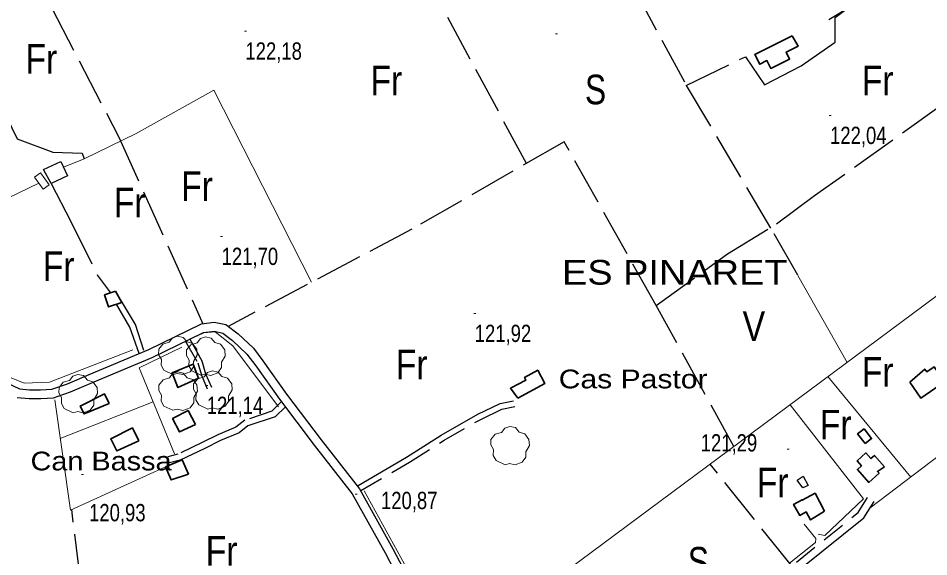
# Model space of a CAD drawing. Extents: x 483855 to 488461, y 4388206 to 4391419.
# Drawn here: x 485066.1 to 485527.5, y 4389100 to 4389372.8 of the extents above; entities that cross this region are included whole.
import ezdxf
from ezdxf.enums import TextEntityAlignment as Align

# ---------------------------------------------------------------- set-up
doc = ezdxf.new("R2010")
doc.units = 0
doc.header["$LTSCALE"] = 4
doc.linetypes.add('LONG_DASHED', pattern=[7.5, 6, -1.5])
doc.linetypes.add('MEDIUM_DASHED', pattern=[4.5, 3, -1.5])
for name, color, linetype, lineweight in [('21', 7, 'Continuous', 25), ('25', 7, 'LONG_DASHED', 25), ('29', 7, 'Continuous', 13), ('36', 7, 'Continuous', 25), ('38', 7, 'Continuous', 25), ('47', 7, 'Continuous', 35), ('51', 7, 'Continuous', 13), ('7', 7, 'Continuous', 13)]:
    doc.layers.add(name, color=color, linetype=linetype, lineweight=lineweight)
doc.layers.add('31', color=7, linetype='Continuous')
doc.layers.add('5', color=7, linetype='Continuous')

msp = doc.modelspace()

# ---------------------------------------------------------------- linework, layer by layer
at = {"layer": '21'}
for points in [[(485078.93, 4389296.12), (485087.7, 4389300.19), (485091.01, 4389293.07), (485082.84, 4389289.15)], [(485460.86, 4389138.84), (485463.86, 4389140.95), (485466.49, 4389136.15), (485463.64, 4389135.02)]]:
    msp.add_lwpolyline(points, close=True, dxfattribs=at)
at = {"layer": '25'}
for p, q in [((485428.79, 4389155.91), (485389.3, 4389227.39)), ((485458.03, 4389095.54), (485416.71, 4389146.95))]:
    msp.add_line(p, q, dxfattribs=at)
for points in [[(485302.1, 4389523.63), (485349.42, 4389440.89), (485404.65, 4389338.81)], [(485323.65, 4389299.28), (485272, 4389394.93), (485227.49, 4389486.7)], [(485069.15, 4389404.46), (485117.24, 4389312.31), (485159.64, 4389218.08)], [(485404.65, 4389338.81), (485434.63, 4389353.26), (485444.25, 4389339.03), (485462.92, 4389348.66), (485480.07, 4389360.62), (485480.13, 4389373.22), (485484.8, 4389376.81)], [(485558.17, 4389345.99), (485469.7, 4389282.81), (485447.41, 4389266.34)], [(485404.65, 4389338.81), (485448.95, 4389263.72), (485461.14, 4389242.59)], [(485057.27, 4389329.54), (485060.13, 4389322.87), (485065.48, 4389311.78), (485083.57, 4389304.98), (485098.49, 4389304.48), (485099.47, 4389301.63)], [(485389.3, 4389227.39), (485342.81, 4389310.28), (485265.54, 4389265.9), (485172.46, 4389216.76)], [(485082.84, 4389289.15), (485092.77, 4389269.89), (485106.32, 4389242.46), (485112.88, 4389233.76)], [(485389.3, 4389227.39), (485425.49, 4389253.41), (485447.14, 4389266.79)], [(485110.93, 4388988.41), (485094.88, 4389085.06), (485097.72, 4389087.76), (485093.16, 4389123.91)]]:
    msp.add_lwpolyline(points, dxfattribs=at)
at = {"layer": '29'}
for points in [[(485144.45, 4389192.38), (485139.91, 4389194.5), (485138.5, 4389197.04), (485138.6, 4389200.02), (485137.23, 4389202.43), (485137.27, 4389205.18), (485139.43, 4389207.78), (485142.62, 4389208.78), (485144.27, 4389210.97), (485146.84, 4389211.8), (485149.7, 4389211.15), (485151.65, 4389208.88), (485154.46, 4389208.06), (485156.59, 4389205.21), (485156.83, 4389202.08), (485154.95, 4389198.93), (485154.95, 4389196.25), (485153.13, 4389193.64), (485149.51, 4389192.3), (485146.74, 4389192.93)], [(485158.55, 4389192.02), (485154.01, 4389194.14), (485152.6, 4389196.68), (485152.7, 4389199.66), (485151.33, 4389202.07), (485151.37, 4389204.82), (485153.53, 4389207.42), (485156.72, 4389208.42), (485158.37, 4389210.61), (485160.94, 4389211.44), (485163.8, 4389210.79), (485165.75, 4389208.52), (485168.56, 4389207.7), (485170.69, 4389204.85), (485170.93, 4389201.72), (485169.05, 4389198.57), (485169.05, 4389195.89), (485167.23, 4389193.28), (485163.61, 4389191.94), (485160.84, 4389192.57)], [(485144.48, 4389174.22), (485139.94, 4389176.34), (485138.53, 4389178.88), (485138.63, 4389181.86), (485137.26, 4389184.27), (485137.3, 4389187.02), (485139.46, 4389189.62), (485142.65, 4389190.62), (485144.3, 4389192.81), (485146.87, 4389193.64), (485149.73, 4389192.99), (485151.68, 4389190.72), (485154.49, 4389189.9), (485156.62, 4389187.05), (485156.86, 4389183.92), (485154.98, 4389180.77), (485154.98, 4389178.09), (485153.16, 4389175.48), (485149.54, 4389174.14), (485146.77, 4389174.77)], [(485162.1, 4389174.85), (485157.56, 4389176.97), (485156.15, 4389179.51), (485156.25, 4389182.49), (485154.88, 4389184.9), (485154.92, 4389187.65), (485157.08, 4389190.25), (485160.27, 4389191.25), (485161.92, 4389193.44), (485164.49, 4389194.27), (485167.35, 4389193.62), (485169.3, 4389191.35), (485172.11, 4389190.53), (485174.24, 4389187.68), (485174.48, 4389184.55), (485172.6, 4389181.4), (485172.6, 4389178.72), (485170.78, 4389176.11), (485167.16, 4389174.77), (485164.39, 4389175.4)], [(485093.92, 4389173.01), (485089.38, 4389175.13), (485087.97, 4389177.67), (485088.07, 4389180.65), (485086.7, 4389183.06), (485086.74, 4389185.81), (485088.9, 4389188.41), (485092.09, 4389189.41), (485093.74, 4389191.6), (485096.31, 4389192.43), (485099.17, 4389191.78), (485101.12, 4389189.51), (485103.93, 4389188.69), (485106.06, 4389185.84), (485106.3, 4389182.71), (485104.42, 4389179.56), (485104.42, 4389176.88), (485102.6, 4389174.27), (485098.98, 4389172.93), (485096.21, 4389173.56)], [(485312.78, 4389146.67), (485308.24, 4389148.79), (485306.83, 4389151.33), (485306.93, 4389154.31), (485305.56, 4389156.72), (485305.6, 4389159.47), (485307.76, 4389162.07), (485310.95, 4389163.07), (485312.6, 4389165.26), (485315.17, 4389166.09), (485318.03, 4389165.44), (485319.98, 4389163.17), (485322.79, 4389162.35), (485324.92, 4389159.5), (485325.16, 4389156.37), (485323.28, 4389153.22), (485323.28, 4389150.54), (485321.46, 4389147.93), (485317.84, 4389146.59), (485315.07, 4389147.22)]]:
    msp.add_lwpolyline(points, close=True, dxfattribs=at)
at = {"layer": '36'}
for points in [[(485060.35, 4389188.07), (485066.67, 4389185.08), (485071.85, 4389184.52), (485077.41, 4389184.53), (485083.04, 4389184.86), (485091.03, 4389187.7), (485101.94, 4389192.33), (485132.2, 4389205.01), (485158.95, 4389217.98), (485165.3, 4389218.86), (485171.29, 4389217.62), (485177.53, 4389213), (485185.28, 4389205.68), (485190.05, 4389199.33), (485202, 4389182.41), (485219.53, 4389159.27), (485239.04, 4389134.38), (485255.93, 4389104.05), (485269.53, 4389078.02)], [(485065.47, 4389180.8), (485071.62, 4389180.14), (485077.54, 4389180.15), (485083.92, 4389180.53), (485092.62, 4389183.62), (485103.64, 4389188.29), (485134, 4389201.02), (485159.93, 4389213.59), (485165.6, 4389214.27), (485169.76, 4389213.3), (485174.71, 4389209.64), (485182, 4389202.75), (485186.51, 4389196.75), (485198.47, 4389179.82), (485216.06, 4389156.6), (485235.38, 4389131.95), (485252.08, 4389101.97), (485265.78, 4389075.74)]]:
    msp.add_lwpolyline(points, dxfattribs=at)
at = {"layer": '38'}
for points in [[(485529.14, 4389398.98), (485520.63, 4389395.56), (485487.6, 4389378.49), (485476.81, 4389372.02)], [(485127.29, 4389202.95), (485122.64, 4389216.38), (485115.8, 4389227.99)], [(485129.79, 4389204.44), (485125.46, 4389217.66), (485118.45, 4389229.55)], [(485152.8, 4389210.52), (485159.15, 4389199.21), (485161.03, 4389192.76), (485163.97, 4389185.94)], [(485201.47, 4389176.05), (485196.34, 4389170.89), (485182.42, 4389166.3), (485178.06, 4389162.83), (485168.57, 4389158.94), (485160.7, 4389154.94), (485148.14, 4389149.01), (485142.77, 4389147.59)], [(485238.3, 4389136.15), (485262.8, 4389150.45), (485280.34, 4389161.58), (485299.07, 4389172.26), (485310.24, 4389177.6), (485317.14, 4389179.11)], [(485357.11, 4389013.94), (485367.28, 4389021.67), (485401.37, 4389048.2), (485435.61, 4389074.06), (485462.81, 4389094.29), (485494.65, 4389119.84), (485499.81, 4389128.1)]]:
    msp.add_lwpolyline(points, dxfattribs=at)
at = {"layer": '38', "linetype": 'MEDIUM_DASHED'}
for points in [[(485150.69, 4389209.49), (485157.03, 4389198.31), (485158.87, 4389191.99), (485161.87, 4389185.03)], [(485199.31, 4389178.44), (485194.6, 4389173.72), (485180.86, 4389169.19), (485176.41, 4389165.65), (485167.23, 4389161.88), (485159.28, 4389157.84), (485147.03, 4389152.06), (485141.94, 4389150.71)], [(485239.78, 4389133.61), (485264.33, 4389147.93), (485281.86, 4389159.06), (485300.44, 4389169.65), (485311.2, 4389174.8), (485317.77, 4389176.23)], [(485323.78, 4388993.44), (485364.93, 4389024.72), (485399.03, 4389051.26), (485433.3, 4389077.14), (485460.45, 4389097.34), (485491.73, 4389122.44), (485496.54, 4389130.14)]]:
    msp.add_lwpolyline(points, dxfattribs=at)
at = {"layer": '47'}
for points in [[(485458.31, 4389363.96), (485439.35, 4389354.47), (485441.84, 4389349.49), (485445.51, 4389351.33), (485447.47, 4389347.4), (485457.02, 4389352.16), (485455.28, 4389355.64), (485461.3, 4389358.67)], [(485115.34, 4389234.59), (485109.79, 4389232.71), (485111.85, 4389226.61), (485118.55, 4389228.88)], [(485157.49, 4389190.56), (485154.7, 4389197.53), (485144.02, 4389193.28), (485147, 4389185.78)], [(485319.24, 4389180.39), (485333.03, 4389187.84), (485329.4, 4389194.55), (485322.67, 4389190.92), (485323.4, 4389189.55), (485315.5, 4389185.36)], [(485517.94, 4389188.52), (485523.5, 4389180.43), (485535.51, 4389188.68), (485530.31, 4389196.24), (485526.56, 4389193.66), (485525.53, 4389195.14)], [(485112.2, 4389177.73), (485109.8, 4389182.53), (485097.49, 4389176.38), (485099.48, 4389172.38)], [(485155.88, 4389167), (485152.12, 4389174.12), (485144.32, 4389170.01), (485147.83, 4389163.32)], [(485127.16, 4389158.78), (485123.93, 4389165.3), (485112.95, 4389159.86), (485116.01, 4389153.66)], [(485495.33, 4389157.43), (485498.56, 4389159.91), (485494.77, 4389164.83), (485491.48, 4389162.29)], [(485505.11, 4389145.59), (485499.99, 4389151.36), (485498.21, 4389149.78), (485495.68, 4389152.61), (485491.18, 4389148.59), (485493.42, 4389146.06), (485491.38, 4389144.27), (485497.13, 4389137.7), (485502.39, 4389142.31), (485501.55, 4389143.26)], [(485152.32, 4389141.94), (485149.23, 4389149.21), (485140.73, 4389145.59), (485143.56, 4389138.94)], [(485474.76, 4389123.19), (485469.95, 4389132.18), (485463.44, 4389128.7), (485463.3, 4389128.95), (485459.04, 4389126.57), (485462.16, 4389120.97), (485465.38, 4389122.77), (485467.66, 4389118.67)]]:
    msp.add_lwpolyline(points, close=True, dxfattribs=at)
at = {"layer": '47', "lineweight": 13}
msp.add_lwpolyline([(485077.43, 4389294.54), (485081.79, 4389288.4), (485078.72, 4389286.22), (485074.36, 4389292.36)], close=True, dxfattribs=at)
at = {"layer": '51'}
for p, q in [((485029.48, 4389266.59), (485076.57, 4389289.26)), ((485486.14, 4389198.47), (485461.14, 4389242.59)), ((485518.37, 4389140.44), (485476.44, 4389191.27)), ((485134.49, 4389178.48), (485087.4, 4389160.02)), ((485497.86, 4389124.8), (485561.35, 4389173.21))]:
    msp.add_line(p, q, dxfattribs=at)
for points in [[(485089.03, 4389297.34), (485099.47, 4389301.63), (485125.78, 4389314.5), (485165.13, 4389336.4), (485214.74, 4389239.09)], [(485023.88, 4389292.36), (485022.38, 4389288.6), (485042.29, 4389226.9), (485051.25, 4389204.03), (485059.6, 4389191.9), (485069.05, 4389188.01), (485081.88, 4389188.56), (485124.16, 4389204.83)], [(485345.26, 4389093.94), (485536.99, 4389236.19), (485571.11, 4389188.11)], [(485198.02, 4389175.92), (485174.87, 4389206.94), (485165.91, 4389214.06), (485160.18, 4389213.39), (485156.57, 4389211.71)], [(485145.25, 4389152.2), (485127.4, 4389195.76), (485149.06, 4389206.14)], [(485084.67, 4389179.56), (485092.49, 4389123.61), (485140.73, 4389145.59)], [(485471.48, 4389111.55), (485474.78, 4389110.89), (485494.4, 4389129.45), (485457.24, 4389177.03)], [(485241.45, 4389133.46), (485265.53, 4389089.61), (485286.91, 4389053.19), (485288.29, 4389052.98), (485345.26, 4389093.94), (485385.85, 4389041.58), (485325.32, 4388995.84), (485290.53, 4389047.84)], [(485464.42, 4389116.64), (485470.28, 4389109.23), (485470.14, 4389107.2), (485457.03, 4389096.75)]]:
    msp.add_lwpolyline(points, dxfattribs=at)
at = {"layer": '7'}
for p, q in [((485180.71, 4389366.2), (485181.71, 4389366.2)), ((485338.32, 4389364.96), (485339.32, 4389364.96)), ((485477.01, 4389323.48), (485478.01, 4389323.48)), ((485168.65, 4389262.21), (485169.65, 4389262.21)), ((485296.91, 4389223.19), (485297.91, 4389223.19)), ((485161.12, 4389186.74), (485162.12, 4389186.74)), ((485455.83, 4389154.59), (485456.83, 4389154.59)), ((485098.19, 4389141.7), (485099.19, 4389141.7)), ((485236.9, 4389131.73), (485237.9, 4389131.73))]:
    msp.add_line(p, q, dxfattribs=at)

# ---------------------------------------------------------------- texts
at = {"layer": '31'}
for s, width, p in [('Fr', 0.85, (485077.8, 4389344.75)), ('Fr', 0.85, (485252.6, 4389333.85)), ('Fr', 0.85, (485501.62, 4389333.85)), ('S', 0.8, (485358.66, 4389329.24)), ('Fr', 0.85, (485156.68, 4389280.33)), ('Fr', 0.85, (485122.55, 4389272.03)), ('Fr', 0.85, (485086.58, 4389239.73)), ('V', 0.85, (485438.91, 4389209.28)), ('Fr', 0.85, (485265.51, 4389189.9)), ('Fr', 0.85, (485501.62, 4389186.21)), ('Fr', 0.85, (485480.41, 4389159.45)), ('Fr', 0.85, (485448.42, 4389130.19)), ('Fr', 0.85, (485169.14, 4389095.55)), ('S', 0.8, (485410.78, 4389090.01))]:
    msp.add_text(s, height=15, dxfattribs=dict(at, width=width)).set_placement(p, align=Align.CENTER)
at = {"layer": '5', "width": 1.15}
for s, height, p in [('ES PINARET', 12.5, (485455.95, 4389237.88)), ('Can Bassa', 9.5, (485143.78, 4389143.79))]:
    msp.add_text(s, height=height, dxfattribs=at).set_placement(p, align=Align.RIGHT)
at = {"layer": '5', "width": 1.2}
msp.add_text('Cas Pastor', height=9.5, dxfattribs=at).set_placement((485340, 4389185.35))
at = {"layer": '7', "width": 0.8}
for s, p in [('122,18', (485181.21, 4389351.83)), ('122,04', (485477.51, 4389309.11)), ('121,70', (485169.15, 4389247.84)), ('121,92', (485297.41, 4389208.82)), ('121,14', (485161.62, 4389172.37)), ('121,29', (485411.96, 4389153.38)), ('120,87', (485249.91, 4389124.19)), ('120,93', (485101.98, 4389118.01))]:
    msp.add_text(s, height=8.75, dxfattribs=at).set_placement(p)

doc.saveas('drawing.dxf')
